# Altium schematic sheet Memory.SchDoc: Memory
size A4; Date: Not used; ApprovedBy: Not used; CheckedBy: Not used; Author: Not used; CompanyName: STMicroelectronics; DrawnBy: Not used; Engineer: Not used; Organization: Not used; Address1: Not used; Address2: Not used; Address3: Not used; Address4: Not used; DocumentNumber: Not used; Revision: Not used; SheetNumber: 7; SheetTotal: 23
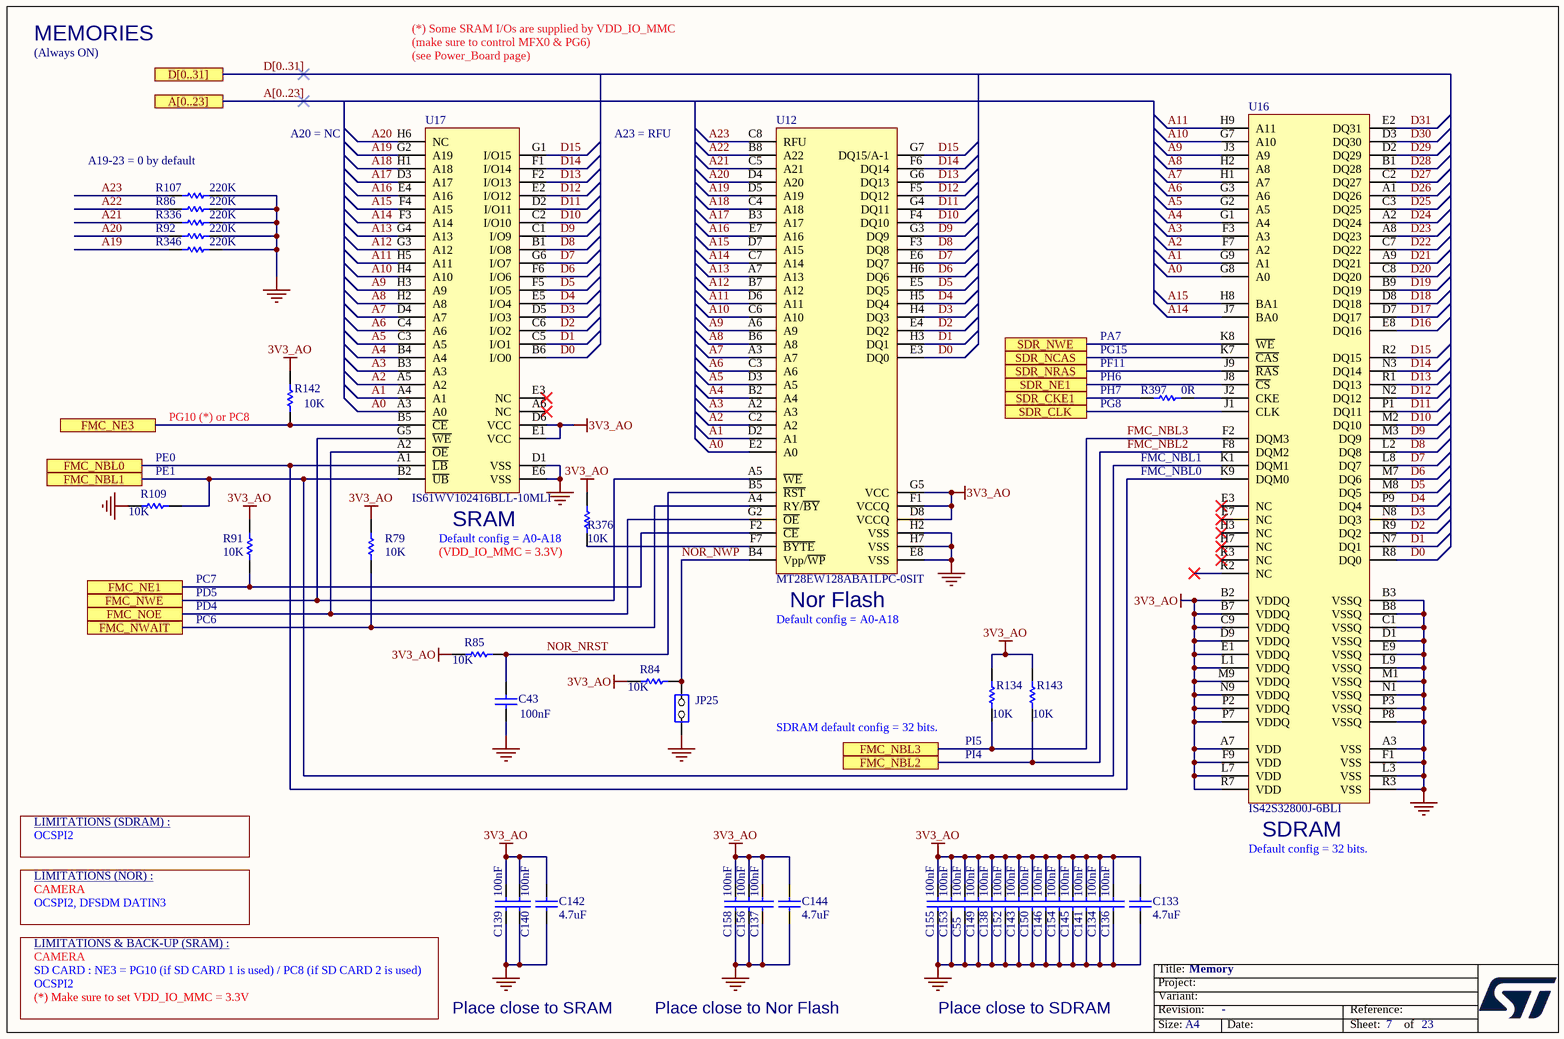
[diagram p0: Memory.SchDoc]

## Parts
C43  value 100nF  [C0402]  (hidden comment: Capacitor)
C55  value 100nF  [C0402]  (hidden comment: Capacitor)
C133  value 4.7uF  [C0603]  (hidden comment: Capacitor)
C134  value 100nF  [C0402]  (hidden comment: Capacitor)
C136  value 100nF  [C0402]  (hidden comment: Capacitor)
C137  value 100nF  [C0402]  (hidden comment: Capacitor)
C138  value 100nF  [C0402]  (hidden comment: Capacitor)
C139  value 100nF  [C0402]  (hidden comment: Capacitor)
C140  value 100nF  [C0402]  (hidden comment: Capacitor)
C141  value 100nF  [C0402]  (hidden comment: Capacitor)
C142  value 4.7uF  [C0603]  (hidden comment: Capacitor)
C143  value 100nF  [C0402]  (hidden comment: Capacitor)
C144  value 4.7uF  [C0603]  (hidden comment: Capacitor)
C145  value 100nF  [C0402]  (hidden comment: Capacitor)
C146  value 100nF  [C0402]  (hidden comment: Capacitor)
C149  value 100nF  [C0402]  (hidden comment: Capacitor)
C150  value 100nF  [C0402]  (hidden comment: Capacitor)
C152  value 100nF  [C0402]  (hidden comment: Capacitor)
C153  value 100nF  [C0402]  (hidden comment: Capacitor)
C154  value 100nF  [C0402]  (hidden comment: Capacitor)
C155  value 100nF  [C0402]  (hidden comment: Capacitor)
C156  value 100nF  [C0402]  (hidden comment: Capacitor)
C158  value 100nF  [C0402]  (hidden comment: Capacitor)
JP25  Jumper_Header 2x1  [CON_SAMTEC_TSW-102-07-G-S]  (value not drawn)
R79  value 10K  [R0402]  (hidden comment: Resistor)
R84  value 10K  [R0402]  (hidden comment: Resistor)
R85  value 10K  [R0402]  (hidden comment: Resistor)
R86  value 220K  [R0402]  (hidden comment: Resistor)
R91  value 10K  [R0402]  (hidden comment: Resistor)
R92  value 220K  [R0402]  (hidden comment: Resistor)
R107  value 220K  [R0402]  (hidden comment: Resistor)
R109  value 10K  [R0402]  (hidden comment: Resistor)
R134  value 10K  [R0402]  (hidden comment: Resistor)
R142  value 10K  [R0402]  (hidden comment: Resistor)
R143  value 10K  [R0402]  (hidden comment: Resistor)
R336  value 220K  [R0402]  (hidden comment: Resistor)
R346  value 220K  [R0402]  (hidden comment: Resistor)
R376  value 10K  [R0402]  (hidden comment: Resistor)
R397  value 0R  [R0402]  (hidden comment: Resistor)
U12  value MT28EW128ABA1LPC-0SIT  [ICC_FBGA64_11X13_P1]  (hidden comment: PC28F128M29EWLA)
U16  value IS42S32800J-6BLI  [ICC_TFBGA90_8X13_P080]  (hidden comment: IS42S32800G-6BLI)
U17  IS61WV102416BLL-10MLI  [ICC_MINI-BGA48_9X11_P075]

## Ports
A[0..23], D[0..31], FMC_NBL0, FMC_NBL1, FMC_NBL2, FMC_NBL3, FMC_NE1, FMC_NE3, FMC_NOE, FMC_NWAIT, FMC_NWE, SDR_CKE1, SDR_CLK, SDR_NCAS, SDR_NE1, SDR_NRAS, SDR_NWE

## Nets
3V3_AO: C55.1 C133.2 C134.1 C136.1 C137.1 C138.1 C139.1 C140.1 C141.1 C142.2 C143.1 C144.2 C145.1 C146.1 C149.1 C150.1 C152.1 C153.1 C154.1 C155.1 C156.1 C158.1 R79.2 R84.2 R85.1 R91.2 R134.2 R142.2 R143.2 R376.2 U12.D8(VCCQ) U12.F1(VCCQ) U12.G5(VCC) U16.A7(VDD) U16.B2(VDDQ) U16.B7(VDDQ) U16.C9(VDDQ) U16.D9(VDDQ) U16.E1(VDDQ) U16.F9(VDD) U16.L1(VDDQ) U16.L7(VDD) U16.M9(VDDQ) U16.N9(VDDQ) U16.P2(VDDQ) U16.P7(VDDQ) U16.R7(VDD) U17.D6(VCC) U17.E1(VCC)
GND: C43.2 C55.2 C133.1 C134.2 C136.2 C137.2 C138.2 C139.2 C140.2 C141.2 C142.1 C143.2 C144.1 C145.2 C146.2 C149.2 C150.2 C152.2 C153.2 C154.2 C155.2 C156.2 C158.2 JP25.1(COMMON) R86.1 R92.1 R107.1 R109.1 R336.1 R346.1 U12.E8(VSS) U12.H2(VSS) U12.H7(VSS) U16.A3(VSS) U16.B3(VSSQ) U16.B8(VSSQ) U16.C1(VSSQ) U16.D1(VSSQ) U16.E9(VSSQ) U16.F1(VSS) U16.L3(VSS) U16.L9(VSSQ) U16.M1(VSSQ) U16.N1(VSSQ) U16.P3(VSSQ) U16.P8(VSSQ) U16.R3(VSS) U17.D1(VSS) U17.E6(VSS)
A0: U12.E2(A0) U16.G8(A0) U17.A3(A0)
A1: U12.D2(A1) U16.G9(A1) U17.A4(A1)
A2: U12.C2(A2) U16.F7(A2) U17.A5(A2)
A3: U12.A2(A3) U16.F3(A3) U17.B3(A3)
A4: U12.B2(A4) U16.G1(A4) U17.B4(A4)
A5: U12.D3(A5) U16.G2(A5) U17.C3(A5)
A6: U12.C3(A6) U16.G3(A6) U17.C4(A6)
A7: U12.A3(A7) U16.H1(A7) U17.D4(A7)
A8: U12.B6(A8) U16.H2(A8) U17.H2(A8)
A9: U12.A6(A9) U16.J3(A9) U17.H3(A9)
A10: U12.C6(A10) U16.G7(A10) U17.H4(A10)
A11: U12.D6(A11) U16.H9(A11) U17.H5(A11)
A12: U12.B7(A12) U17.G3(A12)
A13: U12.A7(A13) U17.G4(A13)
A14: U12.C7(A14) U16.J7(BA0) U17.F3(A14)
A15: U12.D7(A15) U16.H8(BA1) U17.F4(A15)
A16: U12.E7(A16) U17.E4(A16)
A17: U12.B3(A17) U17.D3(A17)
A18: U12.C4(A18) U17.H1(A18)
A19: R346.2 U12.D5(A19) U17.G2(A19)
A20: R92.2 U12.D4(A20) U17.H6(NC)
A21: R336.2 U12.C5(A21)
A22: R86.2 U12.B8(A22)
A23: R107.2 U12.C8(RFU)
D0: U12.E3(DQ0) U16.R8(DQ0) U17.B6(I/O0)
D1: U12.H3(DQ1) U16.N7(DQ1) U17.C5(I/O1)
D2: U12.E4(DQ2) U16.R9(DQ2) U17.C6(I/O2)
D3: U12.H4(DQ3) U16.N8(DQ3) U17.D5(I/O3)
D4: U12.H5(DQ4) U16.P9(DQ4) U17.E5(I/O4)
D5: U12.E5(DQ5) U16.M8(DQ5) U17.F5(I/O5)
D6: U12.H6(DQ6) U16.M7(DQ6) U17.F6(I/O6)
D7: U12.E6(DQ7) U16.L8(DQ7) U17.G6(I/O7)
D8: U12.F3(DQ8) U16.L2(DQ8) U17.B1(I/O8)
D9: U12.G3(DQ9) U16.M3(DQ9) U17.C1(I/O9)
D10: U12.F4(DQ10) U16.M2(DQ10) U17.C2(I/O10)
D11: U12.G4(DQ11) U16.P1(DQ11) U17.D2(I/O11)
D12: U12.F5(DQ12) U16.N2(DQ12) U17.E2(I/O12)
D13: U12.G6(DQ13) U16.R1(DQ13) U17.F2(I/O13)
D14: U12.F6(DQ14) U16.N3(DQ14) U17.F1(I/O14)
D15: U12.G7(DQ15/A-1) U16.R2(DQ15) U17.G1(I/O15)
D16: U16.E8(DQ16)
D17: U16.D7(DQ17)
D18: U16.D8(DQ18)
D19: U16.B9(DQ19)
D20: U16.C8(DQ20)
D21: U16.A9(DQ21)
D22: U16.C7(DQ22)
D23: U16.A8(DQ23)
D24: U16.A2(DQ24)
D25: U16.C3(DQ25)
D26: U16.A1(DQ26)
D27: U16.C2(DQ27)
D28: U16.B1(DQ28)
D29: U16.D2(DQ29)
D30: U16.D3(DQ30)
D31: U16.E2(DQ31)
FMC_NBL0: U16.K9(DQM0) U17.A1(~{LB}) ; port FMC_NBL0
FMC_NBL1: R109.2 U16.K1(DQM1) U17.B2(~{UB}) ; port FMC_NBL1
FMC_NBL2: R143.1 U16.F8(DQM2) ; port FMC_NBL2
FMC_NBL3: R134.1 U16.F2(DQM3) ; port FMC_NBL3
FMC_NE1: R91.1 U12.F2(~{CE}) ; port FMC_NE1
FMC_NE3: R142.1 U17.B5(~{CE}) ; port FMC_NE3
FMC_NOE: U12.G2(~{OE}) U17.A2(~{OE}) ; port FMC_NOE
FMC_NWAIT: R79.1 U12.A4(RY/~{BY}) ; port FMC_NWAIT
FMC_NWE: U12.A5(~{WE}) U17.G5(~{WE}) ; port FMC_NWE
NOR_NRST: C43.1 R85.2 U12.B5(~{RST})
NOR_NWP: JP25.2(NO) R84.1 U12.B4(Vpp/~{WP})
SDR_CKE1: R397.1 ; port SDR_CKE1
SDR_CLK: U16.J1(CLK) ; port SDR_CLK
SDR_NCAS: U16.K7(~{CAS}) ; port SDR_NCAS
SDR_NE1: U16.J8(~{CS}) ; port SDR_NE1
SDR_NRAS: U16.J9(~{RAS}) ; port SDR_NRAS
SDR_NWE: U16.K8(~{WE}) ; port SDR_NWE
NetR376_1: R376.1 U12.F7(~{BYTE})
NetR397_2: R397.2 U16.J2(CKE)

Not connected (* = marked no-connect by the designer): U16 E3(NC)* E7(NC)* H3(NC)* H7(NC)* K2(NC)* K3(NC)*; U17 A6(NC)* E3(NC)*

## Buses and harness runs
bus A[0..23] = port A[0..23]
bus D[0..31] = port D[0..31]

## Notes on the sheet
- MEMORIES
- (Always ON)
- (*) Some SRAM I/Os are supplied by VDD_IO_MMC
  (make sure to control MFX0 & PG6)
  (see Power_Board page)
- A19-23 = 0 by default
- A20 = NC
- A23 = RFU
- PA7
- (near R397) PG15
- (near R397) PF11
- (near R397) PH6
- (near R142) PG10 (*) or PC8
- (near R397) PH7
- (near R397) PG8
- (near R109) PE1
- (near R109) PE0
- FMC_NBL1
- FMC_NBL0
- (near R91) PC7
- (near R376) Default config = A0-A18
- (near R376) (VDD_IO_MMC = 3.3V)
- (near U17) SRAM
- (near R91) PD5
- PC6
- PD4
- Default config = A0-A18
- (near U12) Nor Flash
- (near R134) SDRAM default config = 32 bits.
- (near R134) PI5
- PI4
- OCSPI2
- LIMITATIONS (SDRAM) :
- Default config = 32 bits.
- (near U16) SDRAM
- CAMERA
- LIMITATIONS (NOR) :
- OCSPI2, DFSDM DATIN3
- SD CARD : NE3 = PG10 (if SD CARD 1 is used) / PC8 (if SD CARD 2 is used)
- LIMITATIONS & BACK-UP (SRAM) :
- (*) Make sure to set VDD_IO_MMC = 3.3V
- Place close to SRAM
- Place close to Nor Flash
- Place close to SDRAM

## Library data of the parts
C43 C55 C134 C136-C141 C143 C145 C146 C149 C150 C152-C156 C158 = MCD-00006: Capacitor, MLCC, 100nF, 16V, X7R, 10%, 0402, T=0.5mm; Manufacturer_Part_Number: CC0402KRX7R7BB104; Manufacturer: YAGEO; Alternate_Manufacturer_Part_Number: GCM155R71C104KA55D; Alternate_Manufacturer: MURATA; Part_Preference: Recommended; Partial_Alternate_Internal_Part_Number: MCD-03299; Provided_By: SUBCO; ECCN_US: EAR99; ECCN_EU: NEC; Component_Country_Of_Origin: China; ID: 2474; Order_Code_RS: 9402047; ShowFields: YES
C133 C142 C144 = MCD-04044: Capacitor, MLCC, 4.7uF, 10V, X5R, 20%, 0603, T=0.8mm; Manufacturer_Part_Number: C0603C475M8PAC7040; Manufacturer: KEMET CORPORATION; Part_Preference: Recommended; Component_Country_Of_Origin: Mexico; ShowFields: YES; ID: 6160
JP25 = MCD-00045: Header, 2x1, 2,54mm, VR, TH, Height 5.84mm/2.54mm; Manufacturer_Part_Number: TSW-102-07-G-S; Manufacturer: SAMTEC; Part_Type: Connector; Alternate_Manufacturer_Part_Number: 313102S111116;313102S111116; Alternate_Manufacturer: JIUBABA; LIANYI; Full_Alternate_Internal_Part_Number: MCD-02390; Part_Preference: Recommended; Partial_Alternate_Internal_Part_Number: MCD-02957, MCD-03720; Provided_By: SUBCO; Component_Country_Of_Origin: China, Costa Rica, Malaysia, USA, Vietnam; ID: 2545; Order_Code_RS: 2505044; ShowFields: YES
R79 R84 R85 R91 R109 R134 R142 R143 R376 = MCD-00053: Resistor,10K,0402,1%,1/16W; Manufacturer_Part_Number: RC0402FR-0710KL; Manufacturer: YAGEO; BMS_Part_Number: 9131590; Part_Preference: Recommended; Provided_By: SUBCO; ECCN_US: EAR99; ECCN_EU: NEC; Component_Country_Of_Origin: China; ID: 2539; Order_Code_RS: 9239359; ShowFields: YES
R86 R92 R107 R336 R346 = MCD-00164: Resistor,220K,0402,1%,1/16W; Manufacturer_Part_Number: RC0402FR-07220KL; Manufacturer: YAGEO; Part_Preference: Recommended; Provided_By: SUBCO; ECCN_US: EAR99; ECCN_EU: NEC; Component_Country_Of_Origin: China; ID: 2704; ShowFields: YES
R397 = MCD-00052: Resistor,0R,0402,5%,1/16W; Manufacturer_Part_Number: RC0402JR-070RL; Manufacturer: YAGEO; Part_Preference: Recommended; Provided_By: SUBCO; ECCN_US: EAR99; ECCN_EU: NEC; Component_Country_Of_Origin: China; ID: 2540; Order_Code_RS: 9232516RL; ShowFields: YES
U12 = MCD-01345: NOR FLASH 128Mbit 75ns - 64-ball LBGA (replacing PC28F128M29EWLA); Part_Type: IC; Manufacturer: MICRON; BMS_Part_Number: 9171980; Part_Preference: Recommended; Provided_By: SUBCO; ECCN_US: 3A991; ECCN_EU: NEC; Component_Country_Of_Origin: Singapore°; ID: 3445; ShowFields: YES
U16 = MCD-00562: SDRAM 256MBit 166MHZ 90BGA; Part_Type: IC; Manufacturer: ISSI; Part_Preference: Recommended; Provided_By: SUBCO; ECCN_US: EAR99; ECCN_EU: NEC; Component_Country_Of_Origin: China, Taiwan°°; ID: 3182; ShowFields: YES
U17 = MCD-00560: SRAM 16Mb 10ns 1Mx16 Async SRAM 3.3v; Manufacturer: ISSI; Part_Type: IC; BMS_Part_Number: 9171285; Part_Preference: Recommended; Provided_By: SUBCO; Component_Country_Of_Origin: Taiwan°; ID: 3185; ShowFields: YES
